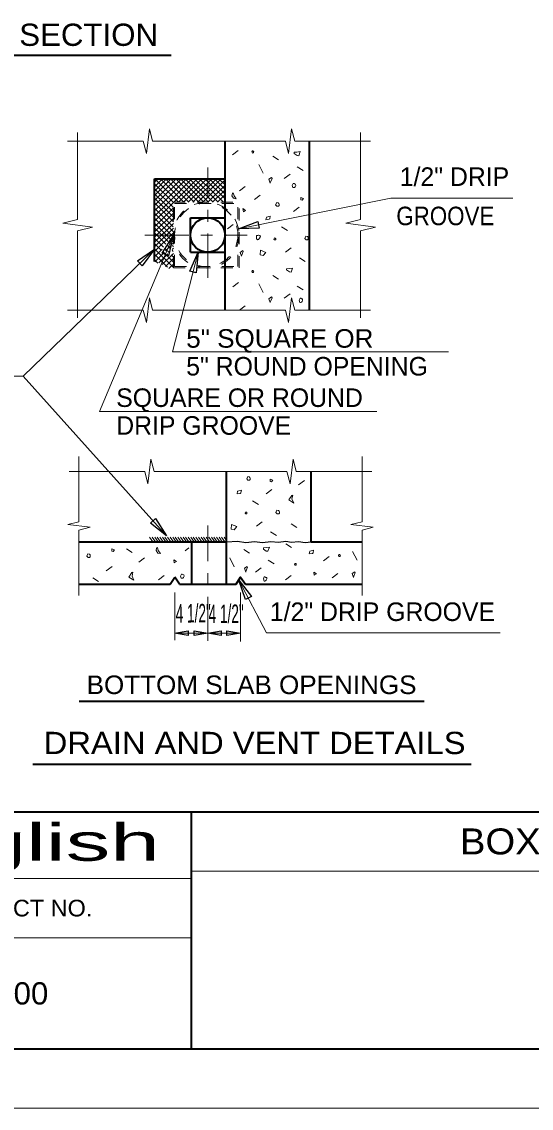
# Model space of a CAD drawing. Extents: x 0 to 34, y 0 to 23.4.
# Drawn here: x 20.82 to 25.11, y 0 to 9.16 of the extents above; entities that cross this region are included whole.
import ezdxf
from ezdxf.enums import TextEntityAlignment as Align

# ---------------------------------------------------------------- set-up
doc = ezdxf.new("R2010")
doc.units = 0
doc.header["$LTSCALE"] = 0.062
doc.linetypes.add('LONG_DASH_SHORT_DASH', pattern=[9.9, 6, -1.2, 1.5, -1.2])
doc.linetypes.add('SHORT_DASHED', pattern=[2.7, 1.5, -1.2])
for name, color, linetype, lineweight in [('1', 7, 'Continuous', 40), ('2', 7, 'SHORT_DASHED', 13), ('4', 7, 'Continuous', 13), ('5', 7, 'LONG_DASH_SHORT_DASH', 13), ('50', 7, 'Continuous', 13), ('7', 7, 'Continuous', 13)]:
    doc.layers.add(name, color=color, linetype=linetype, lineweight=lineweight)

msp = doc.modelspace()

# ---------------------------------------------------------------- linework, layer by layer
at = {"layer": '1', "lineweight": 13}
for p, q in [((21.84307, 8.1549), (21.20505, 8.1549)), ((21.28839, 7.49344), (21.28839, 8.22781)), ((23.04099, 8.1549), (21.9212, 8.1549)), ((23.75714, 8.1549), (23.11911, 8.1549)), ((23.6738, 7.49344), (23.6738, 8.22781)), ((22.51292, 7.83823), (22.53161, 7.83823)), ((21.28839, 6.66531), (21.28839, 7.39969)), ((23.6738, 6.66531), (23.6738, 7.39969)), ((21.84307, 6.7299), (21.20505, 6.7299)), ((23.04099, 6.7299), (21.9212, 6.7299)), ((23.75714, 6.7299), (23.11911, 6.7299)), ((21.30089, 4.94589), (21.30089, 5.49667)), ((23.6863, 4.94589), (23.6863, 5.49667)), ((21.85557, 5.36906), (21.21755, 5.36906)), ((23.05349, 5.36906), (21.9337, 5.36906)), ((23.76964, 5.36906), (23.13161, 5.36906)), ((21.30089, 4.32479), (21.30089, 4.87557)), ((23.6863, 4.32479), (23.6863, 4.87557)), ((22.25, 2), (33.5, 2))]:
    msp.add_line(p, q, dxfattribs=at)
at = {"layer": '1'}
for p, q in [((22.53161, 6.7299), (22.53161, 8.1549)), ((23.24411, 6.7299), (23.24411, 8.1549)), ((21.93786, 7.14016), (21.93786, 7.83823)), ((22.23995, 7.50906), (22.53161, 7.50906)), ((22.23995, 7.2174), (22.23995, 7.50906)), ((22.23995, 7.2174), (22.53161, 7.2174)), ((22.54411, 4.41906), (22.54411, 5.36906)), ((23.25661, 4.77531), (23.25661, 5.36906)), ((21.30089, 4.77531), (22.54411, 4.77531)), ((22.25245, 4.41906), (22.25245, 4.77531)), ((23.25661, 4.77531), (23.6863, 4.77531)), ((21.30089, 4.41906), (22.06896, 4.41906)), ((22.06896, 4.41906), (22.1087, 4.47745)), ((22.14776, 4.41859), (22.1087, 4.47745)), ((22.14776, 4.41906), (22.6251, 4.41906)), ((22.70349, 4.41906), (23.6863, 4.41906)), ((19.25, 2.5), (33.5, 2.5)), ((22.25, 0.5), (22.25, 2.5))]:
    msp.add_line(p, q, dxfattribs=at)
at = {"layer": '1', "linetype": 'LONG_DASH_SHORT_DASH', "lineweight": 13}
msp.add_line((22.38578, 7.00323), (22.38578, 7.93198), dxfattribs=at)
at = {"layer": '1', "lineweight": 35}
for p, q in [((21.93786, 7.83823), (22.53161, 7.83823)), ((23.25661, 4.77531), (23.25484, 4.77547))]:
    msp.add_line(p, q, dxfattribs=at)
at = {"layer": '1', "lineweight": 13}
for points in [[(0, 22), (0, 0), (34, 0)], [(21.84307, 8.1549), (21.86911, 8.05073), (21.89516, 8.25906), (21.9212, 8.1549)], [(23.04099, 8.1549), (23.06703, 8.05073), (23.09307, 8.25906), (23.11911, 8.1549)], [(21.28839, 7.49344), (21.16339, 7.46219), (21.41339, 7.43094), (21.28839, 7.39969)], [(23.6738, 7.49344), (23.5488, 7.46219), (23.7988, 7.43094), (23.6738, 7.39969)], [(21.84307, 6.7299), (21.86911, 6.62573), (21.89516, 6.83406), (21.9212, 6.7299)], [(23.04099, 6.7299), (23.06703, 6.62573), (23.09307, 6.83406), (23.11911, 6.7299)], [(21.85557, 5.36906), (21.88161, 5.2649), (21.90766, 5.47323), (21.9337, 5.36906)], [(23.05349, 5.36906), (23.07953, 5.2649), (23.10557, 5.47323), (23.13161, 5.36906)], [(21.30089, 4.94589), (21.20714, 4.92245), (21.39464, 4.89901), (21.30089, 4.87557)], [(23.6863, 4.94589), (23.59255, 4.92245), (23.78005, 4.89901), (23.6863, 4.87557)]]:
    msp.add_lwpolyline(points, dxfattribs=at)
at = {"layer": '1'}
msp.add_lwpolyline([(33.5, 0.5), (33.5, 21.5), (1.5, 21.5), (1.5, 0.5)], close=True, dxfattribs=at)
at = {"layer": '1', "lineweight": 25}
msp.add_lwpolyline([(22.54411, 4.77531), (22.63693, 4.78073), (22.70745, 4.77062), (22.77969, 4.7799), (22.84849, 4.77062), (22.91901, 4.77906), (22.98286, 4.77234), (23.04328, 4.78073), (23.09198, 4.77234), (23.15073, 4.7799), (23.20786, 4.77062), (23.25661, 4.77531)], dxfattribs=at)
at = {"layer": '1'}
msp.add_lwpolyline([(22.6251, 4.41906), (22.66286, 4.47745), (22.70349, 4.41792)], dxfattribs=at)
msp.add_circle((22.38578, 7.36323), 0.14583, dxfattribs=at)
at = {"layer": '2'}
for p, q in [((22.0962, 7.63938), (22.65052, 7.63938)), ((22.0962, 7.08615), (22.0962, 7.63938)), ((22.10609, 7.09693), (22.10609, 7.63052)), ((22.10609, 7.63052), (22.64047, 7.63052)), ((22.64047, 7.09693), (22.64047, 7.63052)), ((22.65036, 7.08615), (22.65036, 7.64031)), ((22.0962, 7.08563), (22.65036, 7.08563)), ((22.10609, 7.09693), (22.64047, 7.09693))]:
    msp.add_line(p, q, dxfattribs=at)
for centre, radius in [((22.37326, 7.36221), 0.27708), ((22.37326, 7.36434), 0.26719)]:
    msp.add_circle(centre, radius, dxfattribs=at)
at = {"layer": '4', "lineweight": 35}
for p, q in [((16.94776, 8.87938), (22.07755, 8.87938)), ((21.3024, 3.43349), (24.20984, 3.43349)), ((20.91141, 2.9024), (24.60604, 2.9024))]:
    msp.add_line(p, q, dxfattribs=at)
at = {"layer": '4'}
for p, q in [((23.93016, 7.67526), (22.64516, 7.41563)), ((23.93016, 7.67526), (24.95755, 7.67526)), ((21.47292, 5.87385), (22.09563, 7.35781)), ((20.83042, 6.17214), (21.93786, 7.24292)), ((22.08938, 6.37844), (22.30484, 7.2174)), ((22.08938, 6.37844), (24.41536, 6.37844)), ((19.55495, 6.17214), (20.83042, 6.17214)), ((20.83042, 6.17214), (22.03786, 4.82599)), ((21.47292, 5.87385), (23.81141, 5.87385)), ((22.8813, 4.01026), (22.64943, 4.4538)), ((22.1087, 3.94786), (22.1087, 4.35031)), ((22.66286, 3.9363), (22.66286, 4.35031)), ((22.1087, 4.0075), (22.66286, 4.0075)), ((22.8813, 4.01026), (24.84984, 4.01026))]:
    msp.add_line(p, q, dxfattribs=at)
at = {"layer": '4', "lineweight": 25}
for points in [[(22.80708, 7.4774), (22.81839, 7.42151), (22.64516, 7.41563)], [(22.05573, 7.18911), (22.00318, 7.21115), (22.09563, 7.35781)], [(21.83474, 7.10359), (21.79516, 7.14453), (21.93786, 7.24292)], [(22.2899, 7.04469), (22.23469, 7.05885), (22.30484, 7.2174)], [(21.90245, 4.93427), (21.9449, 4.97229), (22.03786, 4.82599)], [(22.75391, 4.31547), (22.70339, 4.28906), (22.64943, 4.4538)], [(22.22094, 4.02563), (22.22094, 3.9876), (22.10693, 4.00661)], [(22.27188, 3.9876), (22.27188, 4.02563), (22.38589, 4.00661)], [(22.4999, 4.02563), (22.4999, 3.9876), (22.38589, 4.00661)], [(22.54729, 3.9876), (22.54729, 4.02563), (22.6613, 4.00661)]]:
    msp.add_lwpolyline(points, close=True, dxfattribs=at)
at = {"layer": '5'}
for p, q in [((21.85479, 7.36323), (22.71911, 7.36323)), ((22.38578, 3.94026), (22.38578, 4.91286))]:
    msp.add_line(p, q, dxfattribs=at)
at = {"layer": '50'}
for p, q in [((19.25, 1.9375), (22.25, 1.9375)), ((19.25, 1.4375), (22.25, 1.4375))]:
    msp.add_line(p, q, dxfattribs=at)
at = {"layer": '7'}
for p, q in [((22.64234, 8.07557), (22.59422, 8.03896)), ((22.93354, 8.02922), (22.98302, 7.99797)), ((22.81604, 7.95844), (22.85271, 7.8849)), ((23.1399, 7.93891), (23.18938, 7.90766)), ((21.93766, 7.80917), (21.96703, 7.83849)), ((21.93802, 7.79604), (22.0963, 7.63859)), ((21.9387, 7.83911), (22.13917, 7.63969)), ((21.93885, 7.65677), (22.12099, 7.83797)), ((21.94005, 7.77344), (22.00521, 7.83823)), ((21.94042, 7.73729), (22.04234, 7.8387)), ((21.94156, 7.70167), (22.07875, 7.83818)), ((21.96682, 7.64089), (22.16516, 7.83818)), ((21.98422, 7.8388), (22.18214, 7.64182)), ((22.01193, 7.64089), (22.21099, 7.83885)), ((22.03057, 7.83766), (22.22786, 7.6412)), ((22.05719, 7.64089), (22.25604, 7.83885)), ((22.07359, 7.83703), (22.27068, 7.64089)), ((22.09964, 7.64089), (22.29813, 7.83839)), ((22.11297, 7.8388), (22.31151, 7.64141)), ((22.13943, 7.63953), (22.33964, 7.83854)), ((22.15542, 7.83818), (22.35323, 7.64141)), ((22.1826, 7.64089), (22.38156, 7.8387)), ((22.19536, 7.83719), (22.39266, 7.64094)), ((22.22161, 7.64089), (22.41979, 7.83807)), ((22.23365, 7.83849), (22.43234, 7.64089)), ((22.2612, 7.64089), (22.45927, 7.83786)), ((22.27531, 7.83781), (22.47484, 7.63938)), ((22.30214, 7.64089), (22.50005, 7.83771)), ((22.31786, 7.83828), (22.51792, 7.63938)), ((22.34516, 7.64089), (22.53109, 7.82578)), ((22.35984, 7.83859), (22.53161, 7.66771)), ((22.40063, 7.83771), (22.53161, 7.7075)), ((22.44057, 7.8387), (22.53161, 7.74807)), ((22.48078, 7.83823), (22.53026, 7.78896)), ((23.07943, 7.87578), (23.0313, 7.83917)), ((21.93792, 7.75396), (22.09641, 7.5962)), ((21.93833, 7.71198), (22.0962, 7.555)), ((22.38755, 7.64089), (22.53161, 7.78411)), ((22.42734, 7.64089), (22.53161, 7.74469)), ((22.46833, 7.64089), (22.53172, 7.70385)), ((22.70281, 7.77385), (22.65469, 7.73724)), ((22.82708, 7.6999), (22.77896, 7.66328)), ((21.93698, 7.63339), (22.09615, 7.47531)), ((21.93724, 7.52151), (22.05719, 7.64089)), ((21.93724, 7.47917), (22.09625, 7.6375)), ((21.9375, 7.56672), (22.01193, 7.64089)), ((21.93792, 7.61208), (21.96682, 7.64089)), ((21.93797, 7.67302), (22.09594, 7.51609)), ((22.09818, 7.63938), (22.09964, 7.64089)), ((22.5238, 7.64057), (22.53214, 7.64885)), ((21.93708, 7.43349), (22.0962, 7.59177)), ((21.93724, 7.39036), (22.09615, 7.54839)), ((21.93802, 7.59031), (22.09599, 7.43339)), ((21.93839, 7.54656), (22.0963, 7.38964)), ((23.15599, 7.5975), (23.10786, 7.56089)), ((21.93688, 7.34563), (22.09609, 7.50391)), ((21.93693, 7.26365), (22.09609, 7.42188)), ((21.93734, 7.42365), (22.05188, 7.30984)), ((21.93771, 7.46464), (22.07068, 7.33245)), ((21.93792, 7.30365), (22.09635, 7.4612)), ((21.93802, 7.50594), (22.09599, 7.34901)), ((22.60104, 7.45318), (22.55292, 7.41656)), ((23.00781, 7.43354), (23.05734, 7.40234)), ((21.93802, 7.3813), (22.0326, 7.2874)), ((21.93802, 7.33688), (22.01438, 7.26099)), ((21.9387, 7.22339), (22.09714, 7.38099)), ((21.93771, 7.2474), (22.09651, 7.08958)), ((21.93802, 7.29214), (21.99656, 7.23401)), ((21.93833, 7.17964), (22.00245, 7.24344)), ((22.02854, 7.24693), (22.06354, 7.21208)), ((22.03141, 7.2288), (22.07646, 7.27396)), ((22.04635, 7.2737), (22.07078, 7.24938)), ((22.06172, 7.30005), (22.07833, 7.28365)), ((22.0863, 7.24135), (22.09615, 7.25115)), ((22.08693, 7.27505), (22.0962, 7.26578)), ((22.08911, 7.28656), (22.0962, 7.29365)), ((22.09188, 7.31146), (22.0962, 7.30708)), ((23.08974, 7.2549), (23.04161, 7.21828)), ((21.93734, 7.15339), (21.96557, 7.12526)), ((21.93839, 7.20057), (22.04698, 7.09255)), ((21.93901, 7.13729), (22.01896, 7.21677)), ((21.97396, 7.12964), (22.04849, 7.20375)), ((22.00208, 7.11359), (22.09641, 7.2074)), ((22.01292, 7.21776), (22.0962, 7.135)), ((22.03036, 7.09823), (22.09542, 7.16297)), ((22.05948, 7.21458), (22.06932, 7.22438)), ((22.07875, 7.19703), (22.09599, 7.17995)), ((22.0849, 7.23542), (22.09599, 7.22438)), ((23.15865, 7.17167), (23.20818, 7.14042)), ((22.05891, 7.08094), (22.09609, 7.11786)), ((22.93354, 7.02188), (22.98302, 6.99063)), ((22.64448, 6.96219), (22.59635, 6.92557)), ((22.81604, 6.95109), (22.85271, 6.87755)), ((23.1399, 6.93156), (23.18938, 6.90031)), ((23.07943, 6.86844), (23.0313, 6.83182)), ((22.70281, 6.76651), (22.65469, 6.7299)), ((23.20057, 5.29349), (23.15245, 5.25687)), ((22.92703, 5.2188), (22.87891, 5.18219)), ((22.76401, 5.12271), (22.81354, 5.09151)), ((22.84594, 4.94406), (22.79781, 4.90745)), ((22.91484, 4.86083), (22.96438, 4.82958)), ((23.08839, 4.92911), (23.13781, 4.89807)), ((21.89557, 4.8149), (21.92349, 4.7762)), ((21.91724, 4.81495), (21.94516, 4.77625)), ((21.93896, 4.81495), (21.96688, 4.77625)), ((21.96068, 4.81495), (21.98859, 4.77625)), ((21.9824, 4.815), (22.01031, 4.7763)), ((22.00406, 4.815), (22.03198, 4.7763)), ((22.02578, 4.815), (22.0537, 4.7763)), ((22.0475, 4.81505), (22.07542, 4.77635)), ((22.06922, 4.81505), (22.09714, 4.77635)), ((22.09094, 4.81505), (22.11885, 4.77635)), ((22.11266, 4.8151), (22.14052, 4.77641)), ((22.13438, 4.8151), (22.16224, 4.77641)), ((22.15609, 4.8151), (22.18396, 4.77641)), ((22.17781, 4.81516), (22.20568, 4.77646)), ((22.19953, 4.81516), (22.22745, 4.77646)), ((22.2212, 4.81516), (22.24911, 4.77646)), ((22.24292, 4.81516), (22.27083, 4.77646)), ((22.26464, 4.81521), (22.29255, 4.77651)), ((22.28635, 4.81521), (22.31427, 4.77651)), ((22.30807, 4.81521), (22.33599, 4.77651)), ((22.32974, 4.81526), (22.35766, 4.77656)), ((22.35146, 4.81526), (22.37938, 4.77656)), ((22.37318, 4.81526), (22.40109, 4.77656)), ((22.3949, 4.81531), (22.42281, 4.77661)), ((22.41661, 4.81531), (22.44453, 4.77661)), ((22.43854, 4.8149), (22.46646, 4.7762)), ((22.46031, 4.8149), (22.48823, 4.7762)), ((22.48104, 4.8149), (22.50896, 4.7762)), ((22.50344, 4.8149), (22.5313, 4.7762)), ((22.52411, 4.8149), (22.54406, 4.78724)), ((21.70083, 4.71646), (21.75031, 4.68521)), ((22.22745, 4.72547), (22.19573, 4.70135)), ((22.68974, 4.71104), (22.73922, 4.67979)), ((23.04344, 4.7601), (23.09286, 4.7288)), ((23.6075, 4.69406), (23.64417, 4.62052)), ((21.85276, 4.6424), (21.80464, 4.60578)), ((22.57224, 4.64026), (22.60891, 4.56672)), ((22.89609, 4.62073), (22.94557, 4.58948)), ((23.40906, 4.65135), (23.36094, 4.61474)), ((21.57922, 4.56771), (21.53109, 4.53109)), ((22.01781, 4.49125), (21.96969, 4.45464)), ((22.83563, 4.5576), (22.7875, 4.52099)), ((23.09026, 4.4926), (23.04214, 4.45599)), ((23.48354, 4.50948), (23.43542, 4.47286)), ((21.4162, 4.47161), (21.46573, 4.44042))]:
    msp.add_line(p, q, dxfattribs=at)
for points in [[(22.75906, 8.06344), (22.76198, 8.05422), (22.76464, 8.05422), (22.76839, 8.05516), (22.77109, 8.05781), (22.77375, 8.06344), (22.77302, 8.06896), (22.76839, 8.0699), (22.76641, 8.07182), (22.76276, 8.07182)], [(23.13766, 8.06297), (23.11557, 8.06109), (23.11557, 8.05005), (23.13953, 8.03354), (23.1525, 8.03167), (23.16542, 8.06661)], [(22.90208, 7.83365), (22.91349, 7.80042), (22.91349, 7.80401), (22.92818, 7.84099), (22.92443, 7.84833)], [(23.0987, 7.78193), (23.10453, 7.76349), (23.10984, 7.76349), (23.11734, 7.76531), (23.12276, 7.77068), (23.12813, 7.78193), (23.12661, 7.79286), (23.11734, 7.79479), (23.11344, 7.79859), (23.10609, 7.79859)], [(22.59365, 7.71453), (22.58958, 7.6938), (22.60333, 7.67349), (22.62635, 7.66896), (22.60797, 7.69333), (22.6001, 7.71865)], [(22.96745, 7.63786), (22.95818, 7.61766), (22.96901, 7.60641), (22.98224, 7.60641), (22.98766, 7.61229), (22.98766, 7.62307), (22.98583, 7.62839), (22.9801, 7.63432)], [(23.17042, 7.67948), (23.16953, 7.65969), (23.18146, 7.65693), (23.19297, 7.67026)], [(22.68266, 7.58594), (22.68635, 7.5601), (22.70484, 7.5712)], [(22.88047, 7.51427), (22.87677, 7.49224), (22.9026, 7.49594), (22.9099, 7.49953), (22.91359, 7.52167)], [(22.79609, 7.35828), (22.79609, 7.33036), (22.80875, 7.32141), (22.8126, 7.325), (22.82344, 7.33609), (22.83083, 7.35089), (22.82547, 7.35828), (22.81807, 7.36182), (22.81448, 7.36182), (22.80724, 7.35979)], [(22.94901, 7.33849), (22.94438, 7.32839), (22.94979, 7.32276), (22.95641, 7.32276), (22.95911, 7.32568), (22.95911, 7.33109), (22.95823, 7.33375), (22.95536, 7.33672)], [(23.21349, 7.35411), (23.20422, 7.33391), (23.21505, 7.32266), (23.22828, 7.32266), (23.2337, 7.32854), (23.2337, 7.33932), (23.23188, 7.34464), (23.22615, 7.35057)], [(22.65849, 7.21698), (22.6699, 7.1838), (22.6699, 7.18734), (22.68458, 7.22438), (22.68083, 7.23172)], [(22.82979, 7.23458), (22.82802, 7.195), (22.85193, 7.18943), (22.87495, 7.21615)], [(22.75906, 7.05609), (22.76198, 7.04688), (22.76464, 7.04688), (22.76839, 7.04781), (22.77109, 7.05047), (22.77375, 7.05609), (22.77302, 7.06161), (22.76839, 7.06255), (22.76641, 7.06448), (22.76276, 7.06448)], [(23.07328, 7.08141), (23.0512, 7.07953), (23.0512, 7.06849), (23.07516, 7.05198), (23.08813, 7.0501), (23.10104, 7.08505)], [(22.90208, 6.8263), (22.91349, 6.79307), (22.91349, 6.79667), (22.92818, 6.83365), (22.92443, 6.84099)], [(23.15667, 6.81328), (23.1625, 6.79484), (23.16781, 6.79484), (23.17531, 6.79667), (23.18073, 6.80203), (23.18609, 6.81328), (23.18458, 6.82422), (23.17531, 6.82615), (23.17141, 6.82995), (23.16406, 6.82995)], [(22.72365, 5.32703), (22.71438, 5.30682), (22.72521, 5.29557), (22.73844, 5.29557), (22.74385, 5.30146), (22.74385, 5.31224), (22.74203, 5.31755), (22.7363, 5.32349)], [(22.91313, 5.30563), (22.91224, 5.28583), (22.92417, 5.28307), (22.93568, 5.29641)], [(22.63667, 5.20344), (22.63297, 5.18141), (22.6588, 5.1851), (22.66609, 5.1887), (22.66979, 5.21083)], [(23.09396, 5.16776), (23.06823, 5.12922), (23.11151, 5.10328), (23.09573, 5.13833), (23.1024, 5.17042)], [(22.96969, 5.04328), (22.96042, 5.02307), (22.97125, 5.01182), (22.98448, 5.01182), (22.9899, 5.01771), (22.9899, 5.02849), (22.98807, 5.0338), (22.98234, 5.03974)], [(22.70521, 5.02766), (22.70057, 5.01755), (22.70599, 5.01193), (22.7126, 5.01193), (22.71531, 5.01484), (22.71531, 5.02026), (22.71443, 5.02292), (22.71156, 5.02589)], [(22.58599, 4.92375), (22.58422, 4.88417), (22.60813, 4.87859), (22.63115, 4.90531)], [(21.37583, 4.67594), (21.36656, 4.65573), (21.3774, 4.64448), (21.39062, 4.64448), (21.39604, 4.65036), (21.39604, 4.66115), (21.39422, 4.66646), (21.38849, 4.6724)], [(21.5788, 4.71755), (21.57792, 4.69776), (21.58984, 4.695), (21.60135, 4.70833)], [(21.95526, 4.72302), (21.9512, 4.70229), (21.96495, 4.68198), (21.98797, 4.67745), (21.96958, 4.70182), (21.96172, 4.72714)], [(22.87786, 4.72755), (22.85578, 4.72568), (22.85578, 4.71464), (22.87974, 4.69813), (22.89271, 4.69625), (22.90563, 4.7312)], [(23.24563, 4.6976), (23.24193, 4.67557), (23.26776, 4.67927), (23.27505, 4.68286), (23.27875, 4.705)], [(22.09943, 4.62401), (22.10313, 4.59818), (22.12161, 4.60927)], [(23.12172, 4.59464), (23.11708, 4.58448), (23.1225, 4.57885), (23.12911, 4.57885), (23.13182, 4.58182), (23.13182, 4.58724), (23.13094, 4.5899), (23.12807, 4.59286)], [(23.48932, 4.66141), (23.49224, 4.65219), (23.4949, 4.65219), (23.49865, 4.65313), (23.50135, 4.65578), (23.50401, 4.66141), (23.50328, 4.66693), (23.49865, 4.66786), (23.49667, 4.66979), (23.49302, 4.66979)], [(21.74615, 4.51667), (21.72042, 4.47813), (21.7637, 4.45219), (21.74792, 4.48724), (21.75458, 4.51932)], [(22.15656, 4.48766), (22.1624, 4.46922), (22.16771, 4.46922), (22.17521, 4.47104), (22.18063, 4.47641), (22.18599, 4.48766), (22.18448, 4.49859), (22.17521, 4.50052), (22.1713, 4.50432), (22.16396, 4.50432)], [(22.69552, 4.55469), (22.70693, 4.52146), (22.70693, 4.52505), (22.72161, 4.56203), (22.71786, 4.56937)], [(23.28063, 4.52089), (23.28432, 4.49505), (23.30281, 4.50615)], [(23.60224, 4.50901), (23.61365, 4.47578), (23.61365, 4.47938), (23.62833, 4.51635), (23.62458, 4.5237)], [(22.8549, 4.46375), (22.86073, 4.44531), (22.86604, 4.44531), (22.87354, 4.44714), (22.87896, 4.4525), (22.88432, 4.46375), (22.88281, 4.47469), (22.87354, 4.47661), (22.86964, 4.48042), (22.86229, 4.48042)]]:
    msp.add_lwpolyline(points, close=True, dxfattribs=at)

# ---------------------------------------------------------------- texts
at = {"layer": '4'}
for s, height, width, p in [('INTERMEDIATE DIAPHRAGM SECTION', 0.1875, 1.05, (19.5319, 8.95813)), ('BOTTOM SLAB OPENINGS', 0.1563, 1.05, (22.75544, 3.49266)), ('DRAIN AND VENT DETAILS', 0.1875, 1.1, (22.78125, 2.98677)), ('BOX GIRDER DETAILS', 0.2188, 1.1, (26.23792, 2.14062))]:
    msp.add_text(s, height=height, dxfattribs=dict(at, width=width)).set_placement(p, align=Align.CENTER)
for s, p in [('1/2" DRIP', (24.00469, 7.77745)), ('5" ROUND OPENING', (22.20469, 6.1788)), ('SQUARE OR ROUND', (21.61474, 5.9137)), ('DRIP GROOVE', (21.61474, 5.67932)), ('1/2" DRIP GROOVE', (22.9099, 4.10885))]:
    msp.add_text(s, height=0.1563, dxfattribs=at).set_placement(p)
for s, width, p in [('GROOVE', 0.9, (23.97552, 7.44604)), ('5" SQUARE OR', 1.05, (22.20469, 6.41318))]:
    msp.add_text(s, height=0.1563, dxfattribs=dict(at, width=width)).set_placement(p)
at = {"layer": '4', "width": 0.55}
for p in [(22.26459, 4.09621), (22.54214, 4.09152)]:
    msp.add_text('4 1/2"', height=0.1562, rotation=0.416, dxfattribs=at).set_placement(p, align=Align.CENTER)
at = {"layer": '50'}
for s, height, width, p in [('English', 0.3125, 1.8, (20.74938, 2.08688)), ('PROJECT NO.', 0.1406, 1.05, (20.74969, 1.6175)), ('0000', 0.1875, 1.05, (20.74969, 0.875))]:
    msp.add_text(s, height=height, dxfattribs=dict(at, width=width)).set_placement(p, align=Align.CENTER)

doc.saveas('drawing.dxf')
